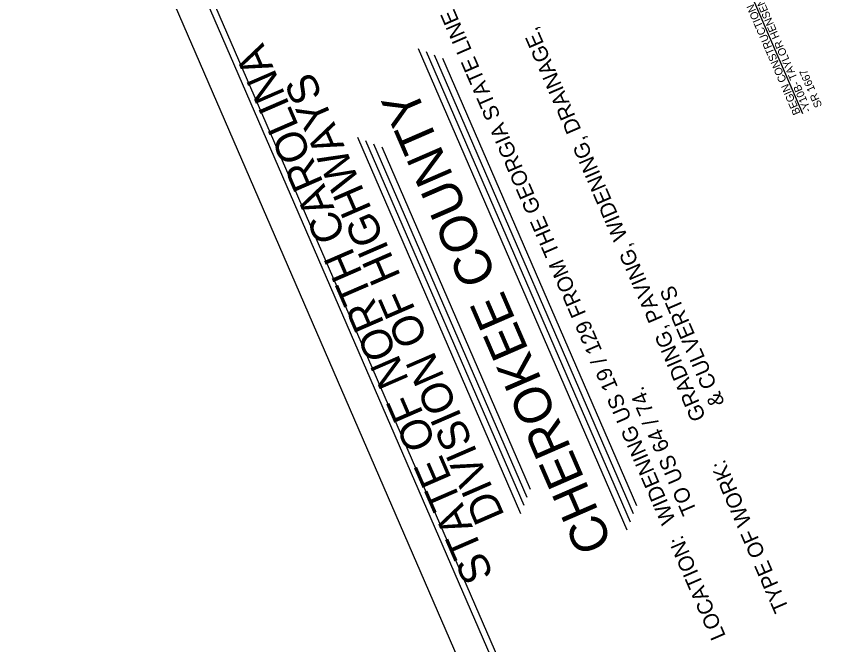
# Model space of a CAD drawing. Extents: x 442728 to 492797, y 479541 to 511293.
# Drawn here: x 465175 to 475139, y 492495 to 500146 of the extents above; entities that cross this region are included whole.
import ezdxf

# ---------------------------------------------------------------- set-up
doc = ezdxf.new("R2010")
doc.units = 0
for name, color, linetype in [('Prop DSN Text', 7, 'Continuous'), ('Sheet Data Field CELL', 7, 'Continuous'), ('Sheet Plot Border Outside CELL', 7, 'Continuous'), ('Sheet Title CELL', 7, 'Continuous')]:
    doc.layers.add(name, color=color, linetype=linetype)

msp = doc.modelspace()

# ---------------------------------------------------------------- linework, layer by layer
at = {"layer": 'Prop DSN Text'}
msp.add_line((474753.6, 498958.8), (474061, 500556.1), dxfattribs=at)
at = {"layer": 'Sheet Plot Border Outside CELL'}
msp.add_lwpolyline([(465175.4, 504729.3), (475224.7, 481554), (490362.8, 488118.1), (480313.5, 511293.4)], close=True, dxfattribs=at)
at = {"layer": 'Sheet Title CELL'}
for p, q in [((472613.6, 493888.4), (470071.6, 499751.1)), ((472652.6, 493987.1), (470170.3, 499712.2)), ((472691.7, 494085.8), (470268.7, 499673.1)), ((472730.5, 494184.4), (470367.6, 499634.2)), ((471318.7, 494089.2), (469332.8, 498668.5)), ((471357.5, 494187.8), (469431.6, 498629.6)), ((471396.6, 494286.5), (469530.1, 498590.5)), ((471435.6, 494385.2), (469628.8, 498551.6))]:
    msp.add_line(p, q, dxfattribs=at)
for points in [[(465680.5, 504507.1), (474512.4, 484138.8)], [(465779.3, 504467.9), (474253, 484926)]]:
    msp.add_lwpolyline(points, dxfattribs=at)

# ---------------------------------------------------------------- texts
at = {"layer": 'Prop DSN Text'}
for s, height, p in [('-Y10B- TAYLOR HENSEN RD.', 94.918, (474859.1, 499001.4)), ('BEGIN CONSTRUCTION', 94.918, (474727.1, 498970)), ('SR 1667', 94.92, (474989.7, 499058.1))]:
    msp.add_text(s, height=height, rotation=113.44243, dxfattribs=at).set_placement(p)
at = {"layer": 'Sheet Data Field CELL'}
for s, height, p in [('WIDENING US 19 / 129 FROM THE GEORGIA STATE LINE', 187.504, (473208.5, 494008.4)), ('GRADING, PAVING, WIDENING, DRAINAGE, ', 187.504, (473576.2, 495264.2)), ('CHEROKEE COUNTY', 450.005, (472441.6, 493723.1)), (' & CULVERTS', 187.504, (473830.8, 495374.6)), ('TO US 64 / 74.', 187.504, (473466.5, 494120.3))]:
    msp.add_text(s, height=height, rotation=113.44243, dxfattribs=at).set_placement(p)
at = {"layer": 'Sheet Title CELL'}
for s, height, p in [('STATE OF NORTH CAROLINA', 375.003, (470990.7, 493339.3)), ('DIVISION OF HIGHWAYS', 375.003, (471124.9, 494066.2)), ('TYPE OF WORK:', 187.504, (474587.1, 492934)), ('LOCATION: ', 187.5, (473817.2, 492600.2))]:
    msp.add_text(s, height=height, rotation=113.44243, dxfattribs=at).set_placement(p)

doc.saveas('drawing.dxf')
